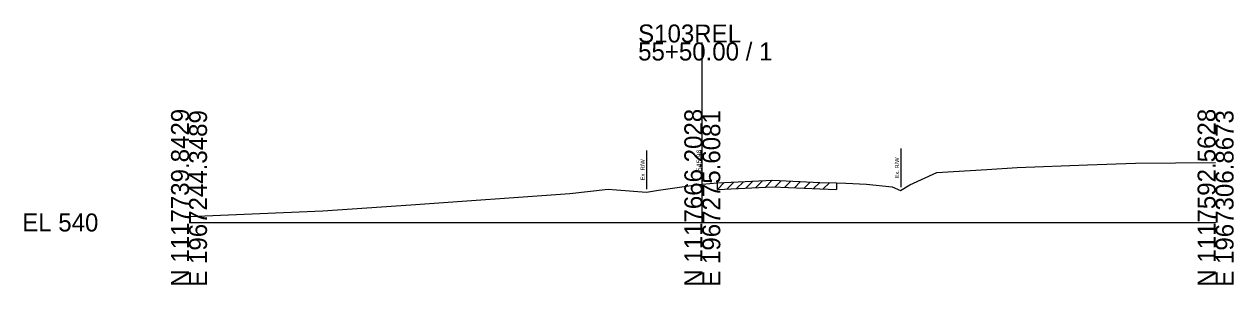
# Model space of a CAD drawing. Extents: x -26 to 163, y -10 to 24518.
# Drawn here: x -25.7 to 162.8, y 5990.3 to 6030.9 of the extents above; entities that cross this region are included whole.
import ezdxf

# ---------------------------------------------------------------- set-up
doc = ezdxf.new("R2010")
doc.units = 0
for name, color, linetype in [('RD_GPK_XS_Cell', 7, 'Continuous'), ('RD_XS_ExGround', 7, 'Continuous'), ('RD_XS_ExPaveRet', 7, 'Continuous'), ('RD_XS_ExRW', 7, 'Continuous'), ('RD_XS_TX_Elev_EX', 7, 'Continuous')]:
    doc.layers.add(name, color=color, linetype=linetype)

msp = doc.modelspace()

# ---------------------------------------------------------------- linework, layer by layer
at = {"layer": 'RD_GPK_XS_Cell'}
for p, q in [((80, 6000), (80, 6028.01)), ((0, 6000), (80, 6000)), ((80, 6000), (160, 6000))]:
    msp.add_line(p, q, dxfattribs=at)
at = {"layer": 'RD_XS_ExGround'}
msp.add_lwpolyline([(0, 6000.92), (20.84, 6001.79), (34.59, 6002.74), (59.35, 6004.5), (65.31, 6005.18), (66.61, 6005.09), (71.3, 6004.7), (73.18, 6005.01), (78.97, 6005.87), (80, 6005.96), (82.35, 6006.15), (88.82, 6006.47), (90.99, 6006.56), (98.33, 6006.23), (100.9, 6006.15), (102.39, 6006.12), (105.57, 6005.98), (109.58, 6005.54), (110.9, 6004.99), (112.34, 6005.88), (116.53, 6007.79), (124.32, 6008.26), (129.07, 6008.58), (140.06, 6008.98), (147.53, 6009.25), (160, 6009.34)], dxfattribs=at)
at = {"layer": 'RD_XS_ExPaveRet'}
for p, q in [((82.35, 6005.15), (83.4, 6006.2)), ((82.35, 6005.15), (82.35, 6006.15)), ((82.35, 6005.15), (88.82, 6005.47)), ((83.85, 6005.23), (84.9, 6006.28)), ((85.35, 6005.3), (86.4, 6006.35)), ((86.85, 6005.37), (87.9, 6006.42)), ((88.35, 6005.44), (89.39, 6006.49)), ((88.82, 6005.47), (90.99, 6005.56)), ((89.85, 6005.51), (90.89, 6006.56)), ((90.99, 6005.56), (98.33, 6005.23)), ((91.35, 6005.55), (92.3, 6006.5)), ((92.85, 6005.48), (93.8, 6006.44)), ((94.35, 6005.41), (95.3, 6006.37)), ((95.85, 6005.34), (96.8, 6006.3)), ((97.35, 6005.28), (98.3, 6006.23)), ((98.33, 6005.23), (100.9, 6005.15)), ((98.85, 6005.22), (99.81, 6006.18)), ((100.9, 6006.15), (100.9, 6005.15))]:
    msp.add_line(p, q, dxfattribs=at)
at = {"layer": 'RD_XS_ExRW'}
for p, q in [((71.29, 6011.21), (71.29, 6005.21)), ((71.29, 6011.2), (71.29, 6005.2)), ((110.92, 6011.5), (110.92, 6005.5))]:
    msp.add_line(p, q, dxfattribs=at)

# ---------------------------------------------------------------- texts
at = {"layer": 'RD_GPK_XS_Cell'}
for s, p in [('S103REL', (70, 6028.01)), ('55+50.00 / 1', (70, 6025.21)), ('EL 540', (-26, 5998.6))]:
    msp.add_text(s, height=2.8, dxfattribs=at).set_placement(p)
for s, p in [('N 1117739.8429', (0, 5990)), ('E 1967244.3489', (2.8, 5990)), ('N 1117666.2028', (80, 5990)), ('E 1967275.6081', (82.8, 5990)), ('N 1117592.5628', (160, 5990)), ('E 1967306.8673', (162.8, 5990))]:
    msp.add_text(s, height=2.8, rotation=90, dxfattribs=at).set_placement(p)
at = {"layer": 'RD_XS_ExRW'}
for p in [(71.04, 6006.55), (71.04, 6006.55), (110.67, 6006.84)]:
    msp.add_text('Ex. R/W ', height=0.65, rotation=90, dxfattribs=at).set_placement(p)
at = {"layer": 'RD_XS_TX_Elev_EX'}
msp.add_text('545.96', height=0.8, rotation=90, dxfattribs=at).set_placement((79.9, 6007.96))

doc.saveas('drawing.dxf')
